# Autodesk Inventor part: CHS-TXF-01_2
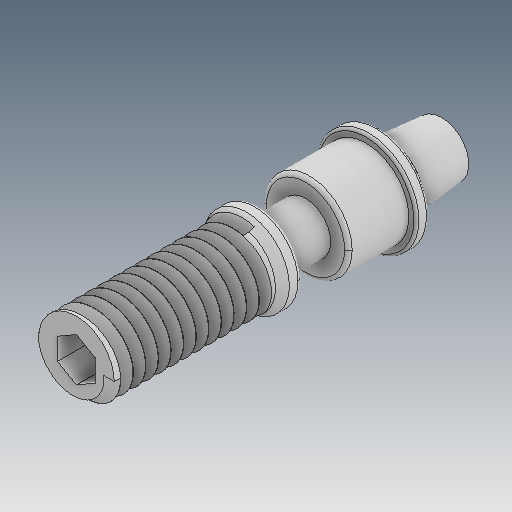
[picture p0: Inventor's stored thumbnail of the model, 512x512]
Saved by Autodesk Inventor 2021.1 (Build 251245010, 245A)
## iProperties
Created: 2019-04
Part Number: CHS-TXF-01_2
Material: Ogólny
Document SubType Name: Modeling
Designer: user
Density: 1 g/cm^3
Appearance: Domyślna
Author: user
Revision Number: ÈÎºÎ
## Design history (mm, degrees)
feature "ÊäÈë1"
node "Bryła1"
